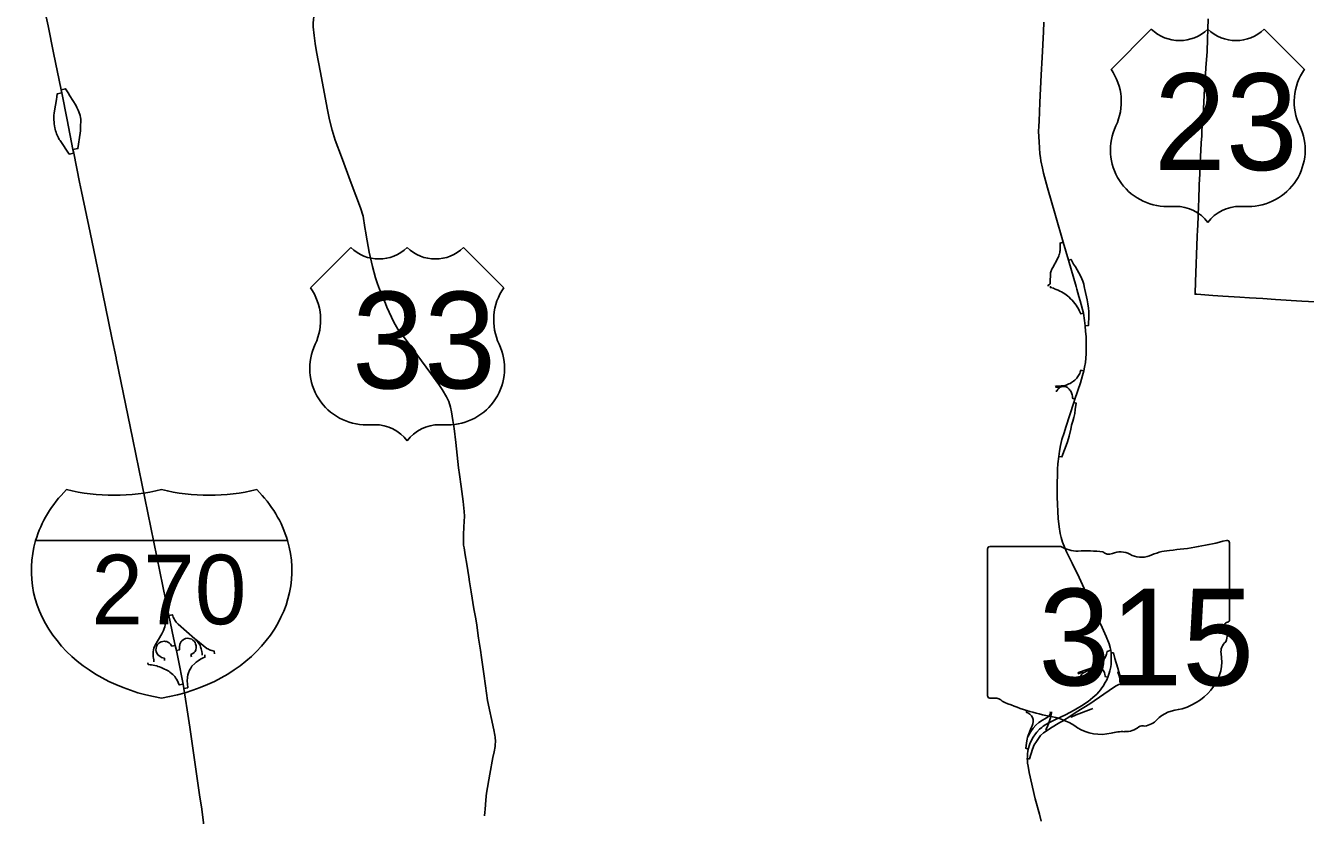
# Model space of a CAD drawing. Extents: x -7.1 to 34, y 0 to 22.
# Drawn here: x 3.881 to 5.586, y 18.117 to 19.169 of the extents above; entities that cross this region are included whole.
import ezdxf

# ---------------------------------------------------------------- set-up
doc = ezdxf.new("R2010")
doc.units = 0
for name, color, linetype in [('GM_X_Interchange_Ramps', 7, 'Continuous'), ('GM_X_Interstate_Route', 7, 'Continuous'), ('GM_X_Interstate_Shield', 7, 'Continuous'), ('GM_X_State_Route', 7, 'Continuous'), ('GM_X_State_Shield', 7, 'Continuous'), ('GM_X_US_Route', 7, 'Continuous'), ('GM_X_US_Shield', 7, 'Continuous')]:
    doc.layers.add(name, color=color, linetype=linetype)

msp = doc.modelspace()

# ---------------------------------------------------------------- linework, layer by layer
at = {"layer": 'GM_X_Interchange_Ramps'}
for points in [[(3.9292, 19.0795), (3.9231, 19.0782), (3.9227, 19.0739), (3.922, 19.0706), (3.9194, 19.0556), (3.9189, 19.0525), (3.9187, 19.0495), (3.9187, 19.0477), (3.9186, 19.0435), (3.9188, 19.0404)], [(3.9543, 19.0464), (3.9536, 19.0491), (3.9517, 19.0543), (3.951, 19.0562), (3.9503, 19.0579), (3.9494, 19.0598), (3.9478, 19.0628), (3.9401, 19.0754), (3.9377, 19.0792), (3.9343, 19.0849), (3.9284, 19.0836)], [(3.9441, 19.0039), (3.9506, 19.0051), (3.9535, 19.0259), (3.954, 19.0286), (3.9542, 19.0307), (3.9543, 19.0329), (3.9546, 19.0443), (3.9543, 19.0464)], [(3.9188, 19.0404), (3.9191, 19.0382), (3.92, 19.0328), (3.9204, 19.0308), (3.921, 19.0287), (3.9215, 19.0268), (3.9222, 19.0249), (3.9229, 19.0231), (3.9237, 19.0212), (3.9247, 19.0193), (3.9258, 19.0174), (3.9268, 19.0159), (3.9391, 18.9979), (3.9451, 18.9991)], [(5.2633, 18.8805), (5.2591, 18.8793), (5.2593, 18.8759), (5.2593, 18.8746), (5.2593, 18.8733), (5.2593, 18.8719), (5.2592, 18.8704), (5.2591, 18.8693), (5.2589, 18.8679), (5.2586, 18.8665), (5.2583, 18.8651), (5.2579, 18.8639), (5.2574, 18.8624), (5.257, 18.8611), (5.2565, 18.8599), (5.2558, 18.8586), (5.2551, 18.8573), (5.2492, 18.8466), (5.2485, 18.8455), (5.248, 18.8444), (5.2475, 18.8433), (5.2471, 18.8421), (5.2467, 18.8408), (5.2465, 18.8395), (5.2463, 18.8385), (5.2462, 18.8376), (5.2462, 18.8369), (5.246, 18.8287), (5.246, 18.8269), (5.2458, 18.8255), (5.2454, 18.8247), (5.2448, 18.8239), (5.2433, 18.8233), (5.2433, 18.822)], [(5.291, 18.8213), (5.2907, 18.8245), (5.2895, 18.8285), (5.2881, 18.8318), (5.2863, 18.8357), (5.284, 18.8398), (5.2794, 18.8474), (5.2771, 18.851), (5.2737, 18.8574), (5.2702, 18.8564)], [(5.2462, 18.8219), (5.2462, 18.8199), (5.2502, 18.819), (5.2518, 18.8184), (5.254, 18.8176), (5.2563, 18.8166), (5.2589, 18.8154), (5.261, 18.8142), (5.2632, 18.813), (5.2654, 18.8115), (5.2673, 18.8102), (5.2691, 18.8088), (5.271, 18.8071), (5.2731, 18.8052), (5.275, 18.8032), (5.277, 18.801), (5.2786, 18.7989), (5.2804, 18.7964), (5.2818, 18.7943), (5.2834, 18.7916), (5.2844, 18.7895), (5.2865, 18.7851), (5.2901, 18.7859)], [(5.2924, 18.7692), (5.297, 18.7695), (5.2974, 18.7827), (5.2973, 18.7883), (5.2969, 18.7927), (5.296, 18.7984), (5.2952, 18.8036), (5.2921, 18.8174), (5.2916, 18.8194), (5.291, 18.8213)], [(5.2905, 18.7092), (5.2869, 18.7099), (5.2858, 18.7072), (5.2852, 18.7057), (5.2845, 18.7044), (5.2836, 18.7028), (5.2828, 18.7014), (5.2812, 18.6991), (5.2797, 18.6976), (5.2785, 18.6965), (5.2771, 18.6954), (5.2757, 18.6944), (5.2741, 18.6934), (5.2725, 18.6924), (5.2708, 18.6916), (5.2691, 18.6909), (5.2672, 18.6902), (5.2655, 18.6897), (5.2636, 18.6893), (5.2625, 18.6892), (5.2606, 18.6889), (5.2584, 18.6888), (5.2561, 18.6886), (5.2537, 18.6886), (5.2527, 18.6882)], [(5.2528, 18.6872), (5.2542, 18.6872), (5.2577, 18.6874), (5.2612, 18.6883), (5.2613, 18.688)], [(5.2534, 18.6819), (5.2546, 18.682), (5.2554, 18.6836), (5.2562, 18.6847), (5.2571, 18.6857), (5.2581, 18.6865), (5.259, 18.6871), (5.2603, 18.6877), (5.2613, 18.688), (5.2617, 18.6881), (5.263, 18.6883), (5.2643, 18.6883), (5.2658, 18.6881), (5.2671, 18.6877), (5.2682, 18.6872), (5.2691, 18.6867), (5.27, 18.686), (5.2707, 18.6853), (5.2713, 18.6846), (5.2722, 18.6835), (5.273, 18.6823), (5.2738, 18.681), (5.2743, 18.6798), (5.2748, 18.6783), (5.2751, 18.677), (5.2754, 18.6754), (5.2754, 18.6727), (5.2789, 18.6715)], [(5.2739, 18.6337), (5.2743, 18.6365), (5.2761, 18.6419), (5.2774, 18.6469), (5.2785, 18.6523), (5.2792, 18.6575), (5.2805, 18.6658), (5.2773, 18.6669)], [(5.2573, 18.595), (5.2616, 18.5943), (5.2651, 18.604), (5.2683, 18.6132), (5.2704, 18.6189), (5.2711, 18.6222), (5.2733, 18.6312), (5.2739, 18.6337)], [(4.0717, 18.3832), (4.0675, 18.3824), (4.0676, 18.3786), (4.0676, 18.3755), (4.0674, 18.3733), (4.0669, 18.3705), (4.0664, 18.3682), (4.0656, 18.3658), (4.0646, 18.3632), (4.0638, 18.3614), (4.0624, 18.3589), (4.0537, 18.3438), (4.0527, 18.3417), (4.052, 18.3396), (4.0514, 18.3373), (4.051, 18.3347), (4.0508, 18.3328), (4.0508, 18.3303), (4.051, 18.3281), (4.0513, 18.3262), (4.0517, 18.324), (4.0518, 18.3212)], [(4.1324, 18.3323), (4.132, 18.3357), (4.1292, 18.3364), (4.1274, 18.3369), (4.126, 18.3375), (4.1247, 18.3381), (4.1236, 18.3386), (4.1224, 18.3394), (4.1079, 18.3512), (4.1066, 18.3522), (4.084, 18.3717), (4.0828, 18.3731), (4.0817, 18.3744), (4.0807, 18.3758), (4.0799, 18.377), (4.0787, 18.3789), (4.0777, 18.3809), (4.0769, 18.3828), (4.0764, 18.3842), (4.0717, 18.3832)], [(4.0662, 18.3231), (4.0658, 18.3263), (4.0637, 18.3268), (4.0618, 18.3274), (4.0597, 18.3288), (4.0576, 18.3305), (4.0558, 18.3328), (4.0549, 18.3351), (4.0546, 18.3372), (4.0547, 18.3393), (4.0554, 18.3419), (4.0567, 18.3444), (4.0583, 18.3462), (4.0599, 18.3473), (4.0616, 18.3481), (4.0638, 18.3487), (4.0659, 18.3489), (4.0675, 18.3487), (4.0692, 18.3483), (4.0705, 18.3477), (4.0721, 18.3468), (4.0732, 18.3458), (4.0742, 18.3448), (4.0758, 18.3424), (4.0803, 18.3433)], [(4.0818, 18.3367), (4.0861, 18.3376), (4.086, 18.3409), (4.0865, 18.3448), (4.0873, 18.3469), (4.0883, 18.3484), (4.0892, 18.3495), (4.0907, 18.3508), (4.0924, 18.3518), (4.0941, 18.3524), (4.0961, 18.3528), (4.0985, 18.3527), (4.1006, 18.3522), (4.1024, 18.3514), (4.1038, 18.3505), (4.1054, 18.3489), (4.1067, 18.3471), (4.1074, 18.3453), (4.108, 18.3428), (4.1084, 18.3401), (4.1078, 18.3374), (4.1068, 18.3353), (4.1056, 18.334), (4.1039, 18.3325), (4.1013, 18.331), (4.1019, 18.3281)], [(4.1161, 18.3303), (4.1161, 18.3324), (4.1159, 18.3351), (4.1155, 18.3371), (4.115, 18.3387), (4.1146, 18.3401), (4.1141, 18.3416), (4.1134, 18.3431), (4.1129, 18.3442), (4.112, 18.3455), (4.1104, 18.3474), (4.1074, 18.3506), (4.1079, 18.3512)], [(4.0917, 18.2858), (4.097, 18.2868), (4.0966, 18.292), (4.0963, 18.2957), (4.0967, 18.3009), (4.0973, 18.3043), (4.0981, 18.3069), (4.0994, 18.3102), (4.1009, 18.313), (4.1025, 18.3155), (4.1063, 18.3192), (4.1081, 18.3209), (4.1107, 18.3228), (4.1141, 18.3249), (4.1175, 18.3266), (4.1199, 18.3275), (4.1196, 18.3306)], [(5.3266, 18.3368), (5.3217, 18.335), (5.3208, 18.3315), (5.3198, 18.3288), (5.3184, 18.326), (5.3168, 18.3237), (5.3146, 18.321), (5.3125, 18.319), (5.3099, 18.3171), (5.307, 18.3159), (5.304, 18.3145), (5.2837, 18.307), (5.2825, 18.3067)], [(5.3443, 18.2944), (5.3443, 18.2975), (5.3426, 18.2986), (5.3408, 18.3), (5.3392, 18.302), (5.3386, 18.3036), (5.3371, 18.3079), (5.3358, 18.3131), (5.3321, 18.3258), (5.3302, 18.3333), (5.327, 18.3332)], [(4.044, 18.3203), (4.0443, 18.3178), (4.0468, 18.3176), (4.0489, 18.3173), (4.0509, 18.317), (4.0531, 18.3165), (4.0556, 18.3159), (4.0573, 18.3154), (4.0595, 18.3146), (4.0615, 18.3139), (4.0633, 18.3131), (4.0651, 18.3123), (4.0692, 18.3103), (4.0717, 18.3088), (4.0733, 18.3078), (4.0754, 18.3061), (4.0772, 18.3045), (4.0786, 18.303), (4.0797, 18.3017), (4.0808, 18.3003), (4.0822, 18.2982), (4.0834, 18.296), (4.0843, 18.294), (4.0856, 18.2907), (4.0907, 18.2916)], [(5.2835, 18.3016), (5.2863, 18.3019), (5.2871, 18.3036), (5.2877, 18.3045), (5.289, 18.306), (5.2902, 18.3068), (5.2927, 18.308), (5.306, 18.3138), (5.3087, 18.314), (5.311, 18.3135), (5.3128, 18.313), (5.3145, 18.3118), (5.3158, 18.3107), (5.3172, 18.3088), (5.3184, 18.3067), (5.3188, 18.3049), (5.3189, 18.3025), (5.3188, 18.302), (5.3228, 18.301)], [(5.2154, 18.1924), (5.2184, 18.1923), (5.2223, 18.205), (5.2247, 18.2108), (5.2275, 18.2155), (5.233, 18.2231), (5.2369, 18.2267), (5.2417, 18.23), (5.2443, 18.2317), (5.2463, 18.2329), (5.2587, 18.2404), (5.2624, 18.2424), (5.2734, 18.2493), (5.2805, 18.2542), (5.2986, 18.2654), (5.3302, 18.2874), (5.3337, 18.2894), (5.3373, 18.2911), (5.3399, 18.2919), (5.3443, 18.2928), (5.3443, 18.2944)], [(5.2829, 18.3053), (5.2842, 18.3057), (5.2899, 18.3078), (5.2902, 18.3068)], [(5.3387, 18.2941), (5.3387, 18.2964), (5.3385, 18.2986), (5.3382, 18.3007), (5.3376, 18.3026), (5.336, 18.3076), (5.3371, 18.3079)], [(5.2142, 18.2573), (5.2141, 18.254), (5.2162, 18.2533), (5.2188, 18.2516), (5.2211, 18.2495), (5.2224, 18.2474), (5.2234, 18.2447), (5.2234, 18.2418), (5.2229, 18.239), (5.2218, 18.2361), (5.2203, 18.2327), (5.2184, 18.2279), (5.2164, 18.2231), (5.2157, 18.2206), (5.2153, 18.2188), (5.2141, 18.2129), (5.2133, 18.2063), (5.2166, 18.2051)], [(5.246, 18.255), (5.2461, 18.2532), (5.2454, 18.251), (5.2444, 18.2495), (5.243, 18.2483), (5.2409, 18.247), (5.2386, 18.2455), (5.2356, 18.2438), (5.2309, 18.2404), (5.2269, 18.237), (5.2234, 18.2332), (5.2208, 18.2298), (5.2188, 18.2265), (5.217, 18.2228), (5.2164, 18.2231)], [(5.2417, 18.23), (5.24, 18.2315), (5.2422, 18.2351), (5.244, 18.2402), (5.2463, 18.2469), (5.2478, 18.2534), (5.2477, 18.2549)], [(5.2734, 18.2493), (5.274, 18.2479), (5.2805, 18.2507), (5.3005, 18.2582), (5.3026, 18.2592)]]:
    msp.add_lwpolyline(points, dxfattribs=at)
at = {"layer": 'GM_X_Interstate_Route'}
for points in [[(3.9183, 19.1329), (3.911, 19.1685), (3.9056, 19.1928), (3.904, 19.2036), (3.9021, 19.2142), (3.8999, 19.2445), (3.9014, 19.2729), (3.9017, 19.2781)], [(3.9365, 19.0435), (3.9292, 19.0795), (3.9284, 19.0836), (3.9183, 19.1329)], [(3.9554, 18.9479), (3.9526, 18.9606), (3.9451, 18.9991), (3.9441, 19.0039), (3.9365, 19.0435)], [(4.0017, 18.7256), (4.0016, 18.7263), (3.996, 18.7532), (3.9795, 18.8336), (3.9671, 18.8932), (3.9554, 18.9479)], [(4.0781, 18.3533), (4.0717, 18.3832), (4.024, 18.6177), (4.0017, 18.7256)], [(4.0997, 18.2345), (4.0963, 18.2577), (4.0917, 18.2858), (4.0907, 18.2916), (4.084, 18.3255), (4.0818, 18.3367), (4.0803, 18.3433), (4.0781, 18.3533)], [(4.1132, 18.1411), (4.0997, 18.2345)], [(4.1272, 18.0359), (4.1226, 18.0721), (4.1151, 18.1281), (4.1132, 18.1411)]]:
    msp.add_lwpolyline(points, dxfattribs=at)
at = {"layer": 'GM_X_Interstate_Shield'}
msp.add_line((4.2299, 18.4829), (3.8944, 18.4829), dxfattribs=at)
msp.add_line((4.2299, 18.4829), (3.8944, 18.4829), dxfattribs=at)
for centre, start_param, end_param in [((4.1055, 18.4432), 2.47259, 2.911027), ((3.9988, 18.7168), 4.415841, 5.008937), ((4.1255, 18.7168), 4.415841, 5.008937), ((4.0188, 18.4432), 0.230566, 0.669003), ((4.1055, 18.4432), 2.911027, 4.511031), ((4.0188, 18.4432), 4.913747, 6.513751)]:
    msp.add_ellipse(centre, major_axis=(0.2169, 0), ratio=0.8, start_param=start_param, end_param=end_param, dxfattribs=at)
at = {"layer": 'GM_X_State_Route'}
for points in [[(5.2321, 19.0664), (5.2337, 19.1036), (5.2351, 19.1264), (5.237, 19.1605), (5.2375, 19.1736)], [(5.2308, 19.0348), (5.2311, 19.0415), (5.2321, 19.0664)], [(5.2328, 18.9934), (5.2321, 18.9983), (5.2311, 19.0142), (5.2305, 19.0277), (5.2308, 19.0348)], [(5.2805, 18.8212), (5.2702, 18.8564), (5.2633, 18.8805), (5.2531, 18.9159), (5.2423, 18.953), (5.2371, 18.9726), (5.2356, 18.979), (5.2334, 18.989), (5.2328, 18.9934)], [(5.234, 18.109), (5.2315, 18.1183), (5.2258, 18.1387), (5.2178, 18.1738), (5.2164, 18.1823), (5.2157, 18.1866), (5.2155, 18.1896), (5.2154, 18.1924), (5.2155, 18.195), (5.2157, 18.1991), (5.2161, 18.2021), (5.2166, 18.2051), (5.2188, 18.212), (5.2211, 18.2172), (5.2234, 18.2211), (5.2263, 18.2255), (5.2279, 18.2276), (5.2317, 18.2316), (5.2349, 18.2341), (5.2367, 18.2355), (5.2401, 18.238), (5.244, 18.2402), (5.2521, 18.2443), (5.2663, 18.251), (5.2778, 18.2571), (5.2876, 18.2628), (5.2966, 18.2685), (5.3029, 18.2738), (5.3078, 18.2784), (5.3107, 18.2815), (5.3131, 18.2843), (5.3146, 18.2866), (5.3165, 18.2891), (5.3191, 18.2937), (5.3212, 18.2976), (5.3228, 18.301), (5.3245, 18.3064), (5.3255, 18.3095), (5.3265, 18.3148), (5.327, 18.3182), (5.3273, 18.3223), (5.3273, 18.327), (5.327, 18.3316), (5.327, 18.3332), (5.3266, 18.3368), (5.3257, 18.3404), (5.3244, 18.3454), (5.3205, 18.355), (5.315, 18.367), (5.3026, 18.3937), (5.2845, 18.4336), (5.2752, 18.4528), (5.2675, 18.4681), (5.2622, 18.4809), (5.2604, 18.4872), (5.2591, 18.4925), (5.2577, 18.5013), (5.2565, 18.5124), (5.2552, 18.5409), (5.255, 18.5521), (5.2558, 18.5783), (5.2561, 18.5851), (5.2573, 18.595), (5.2582, 18.6021), (5.2596, 18.6096), (5.2616, 18.6175), (5.2643, 18.6265), (5.2666, 18.634), (5.2773, 18.6669), (5.2789, 18.6715), (5.2862, 18.6931), (5.2889, 18.7028), (5.2905, 18.7092), (5.2917, 18.7141), (5.2929, 18.72), (5.2938, 18.7319), (5.2939, 18.7448), (5.2936, 18.7549), (5.293, 18.7616), (5.2924, 18.7692), (5.2918, 18.776), (5.2901, 18.7859), (5.2858, 18.8022), (5.2841, 18.8082)], [(5.2841, 18.8082), (5.2814, 18.818), (5.2805, 18.8212)]]:
    msp.add_lwpolyline(points, dxfattribs=at)
at = {"layer": 'GM_X_State_Shield'}
for p, q in [((5.1625, 18.4718), (5.1625, 18.2762)), ((5.2601, 18.4752), (5.1657, 18.4752)), ((5.4847, 18.3777), (5.4847, 18.48)), ((5.4846, 18.3777), (5.4847, 18.3777))]:
    msp.add_line(p, q, dxfattribs=at)
for centre, major_axis, start_param, end_param in [((5.3699, 18.7418), (0.3416, 0), 4.814394, 5.042369), ((5.4811, 18.4804), (0.00359, 0), 6.141152, 7.989035), ((5.1662, 18.4722), (0.00373, 0), 1.712693, 3.28349), ((5.2825, 18.4979), (0.0362, 0), 4.042523, 4.731795), ((5.2945, 18.3654), (0.1299, 0), 1.404758, 1.657858), ((5.324, 18.4732), (0.0104, 0), 3.836095, 5.185415), ((5.3393, 18.4506), (0.0217, 0), 0.950623, 2.079405), ((5.3674, 18.4816), (0.0261, 0), 4.081561, 5.145723), ((5.4135, 18.4154), (0.0687, 0), 1.699011, 2.107814), ((5.4838, 18.3702), (0.00555, 0), 1.883978, 3.671073), ((5.4485, 18.3572), (0.0333, 0), 5.934695, 6.695948), ((5.4808, 18.3773), (0.00384, 0), 5.05454, 6.418171), ((5.4975, 18.3349), (0.0242, 0), 2.387724, 3.262537), ((5.3891, 18.3219), (0.0854, 0), 5.101752, 6.440018), ((5.1663, 18.2758), (0.00376, 0), 3.00124, 4.508301), ((5.1668, 18.2958), (0.0287, 0), 4.665946, 4.897461), ((5.1727, 18.2649), (0.0104, 0), 0.519207, 1.627899), ((5.3035, 18.4407), (0.2467, 0), 4.195997, 4.488961), ((5.23, 18.1883), (0.0772, 0), 0.823519, 1.323587), ((5.3658, 18.2573), (0.0276, 0), 4.937069, 5.64225), ((5.4251, 18.2213), (0.0468, 0), 1.647645, 2.488434), ((5.3134, 18.264), (0.049, 0), 4.026481, 4.996735), ((5.3417, 18.1963), (0.0402, 0), 1.495662, 1.94098), ((5.3453, 18.2493), (0.0261, 0), 4.691044, 5.507374), ((5.3689, 18.2304), (0.00735, 0), 1.147584, 2.315152)]:
    msp.add_ellipse(centre, major_axis=major_axis, ratio=0.8, start_param=start_param, end_param=end_param, dxfattribs=at)
at = {"layer": 'GM_X_US_Route'}
for points in [[(4.2705, 19.2204), (4.2685, 19.2066), (4.2654, 19.185), (4.2639, 19.1726), (4.2639, 19.1674), (4.2652, 19.156), (4.2669, 19.145), (4.2686, 19.1339), (4.2737, 19.1065), (4.2828, 19.0591), (4.286, 19.0435), (4.2894, 19.0298), (4.2935, 19.0164), (4.3018, 18.9942), (4.3146, 18.9592), (4.327, 18.9263), (4.3307, 18.9151)], [(5.4471, 19.0122), (5.4472, 19.0131), (5.4477, 19.0215), (5.4481, 19.0293), (5.4488, 19.04), (5.449, 19.0435), (5.449, 19.0442), (5.4499, 19.0586), (5.4521, 19.0935), (5.4522, 19.0956), (5.4534, 19.1129), (5.4548, 19.1346), (5.4554, 19.1508), (5.4558, 19.1644), (5.4562, 19.1778)], [(5.4413, 18.811), (5.439, 18.8111), (5.4389, 18.8121), (5.4395, 18.8277), (5.4418, 18.8879), (5.4423, 18.8969), (5.4425, 18.9028), (5.4435, 18.9289), (5.4438, 18.937), (5.4445, 18.9568), (5.4451, 18.9716), (5.4453, 18.9772), (5.4456, 18.9859), (5.4456, 18.9868), (5.4461, 18.9944), (5.4471, 19.012), (5.4471, 19.0122)], [(4.3307, 18.9151), (4.333, 18.8998), (4.334, 18.8928), (4.3345, 18.8897), (4.3387, 18.867)], [(4.3387, 18.867), (4.3433, 18.8481), (4.3473, 18.833), (4.3499, 18.8248), (4.3526, 18.8179), (4.3603, 18.7987), (4.3621, 18.7939), (4.3717, 18.7741), (4.3769, 18.7646), (4.3898, 18.7479), (4.421, 18.7057), (4.4316, 18.6909), (4.436, 18.6842), (4.4418, 18.6745), (4.4447, 18.668), (4.4471, 18.6606), (4.4484, 18.6545), (4.4501, 18.6431), (4.4517, 18.6321), (4.4539, 18.6138), (4.4576, 18.5798), (4.4589, 18.5708)], [(5.6556, 18.7977), (5.6518, 18.7978), (5.6164, 18.8001), (5.5811, 18.8019), (5.5458, 18.8042), (5.5293, 18.8053), (5.5112, 18.8065), (5.4986, 18.8073), (5.476, 18.8087), (5.4625, 18.8096), (5.4413, 18.811)], [(4.4589, 18.5708), (4.461, 18.5548), (4.4638, 18.535), (4.4654, 18.5216), (4.4657, 18.5155), (4.4649, 18.5012), (4.4644, 18.4905), (4.4642, 18.4866), (4.4641, 18.4818), (4.4644, 18.4777), (4.4645, 18.4769)], [(4.4645, 18.4769), (4.465, 18.4733), (4.4664, 18.4641), (4.4686, 18.4517), (4.4712, 18.4348), (4.4724, 18.4282), (4.4745, 18.4148), (4.4782, 18.392), (4.4806, 18.3786), (4.4819, 18.3701), (4.4844, 18.3531), (4.4868, 18.337), (4.4881, 18.3272), (4.4914, 18.3053), (4.4934, 18.2896), (4.4963, 18.2698)], [(4.4963, 18.2698), (4.4963, 18.2698), (4.5048, 18.2308), (4.5061, 18.2236), (4.5064, 18.2211), (4.5066, 18.2193), (4.5068, 18.217), (4.5068, 18.2144), (4.5067, 18.2118), (4.5063, 18.2087), (4.5052, 18.2016), (4.5036, 18.1938), (4.4994, 18.1716), (4.4949, 18.1465), (4.4945, 18.1423), (4.4935, 18.1312), (4.4932, 18.1249), (4.4929, 18.1212), (4.4925, 18.1162)]]:
    msp.add_lwpolyline(points, dxfattribs=at)
at = {"layer": 'GM_X_US_Shield'}
for p, q in [((5.3806, 19.1644), (5.327, 19.1107)), ((5.5847, 19.1107), (5.531, 19.1644)), ((5.4021, 18.9282), (5.4129, 18.9282)), ((5.4988, 18.9282), (5.5095, 18.9282)), ((4.3141, 18.8735), (4.2604, 18.8198)), ((4.5181, 18.8198), (4.4644, 18.8735)), ((4.3356, 18.6373), (4.3463, 18.6373)), ((4.4322, 18.6373), (4.4429, 18.6373))]:
    msp.add_line(p, q, dxfattribs=at)
for centre, radius, start, end in [((5.4182, 19.2027), 0.0537, 225.573, 314.427), ((5.4934, 19.2027), 0.0537, 225.573, 314.427), ((5.2654, 19.0676), 0.0752, 334.5471, 35.0009), ((5.6462, 19.0676), 0.0752, 144.9991, 205.4529), ((5.4013, 19.0033), 0.0752, 154.8319, 270.6383), ((5.5103, 19.0033), 0.0752, 269.3617, 25.1681), ((5.4129, 18.8745), 0.0537, 36.8699, 90), ((5.4988, 18.8745), 0.0537, 90, 143.1301), ((4.3517, 18.9118), 0.0537, 225.573, 314.427), ((4.4268, 18.9118), 0.0537, 225.573, 314.427), ((4.1988, 18.7767), 0.0752, 334.5471, 35.0009), ((4.5797, 18.7767), 0.0752, 144.9991, 205.4529), ((4.3347, 18.7124), 0.0752, 154.8319, 270.6383), ((4.4438, 18.7124), 0.0752, 269.3617, 25.1681), ((4.3463, 18.5836), 0.0537, 36.8699, 90), ((4.4322, 18.5836), 0.0537, 90, 143.1301)]:
    msp.add_arc(centre, radius, start, end, dxfattribs=at)

# ---------------------------------------------------------------- texts
at = {"layer": 'GM_X_Interstate_Shield'}
msp.add_text('270', height=0.09255, dxfattribs=at).set_placement((3.9687, 18.3715))
at = {"layer": 'GM_X_State_Shield'}
msp.add_text('315', height=0.12885, dxfattribs=at).set_placement((5.2301, 18.29))
at = {"layer": 'GM_X_US_Shield'}
for s, p in [('23', (5.3841, 18.9765)), ('33', (4.3159, 18.6856))]:
    msp.add_text(s, height=0.12885, dxfattribs=at).set_placement(p)

doc.saveas('drawing.dxf')
